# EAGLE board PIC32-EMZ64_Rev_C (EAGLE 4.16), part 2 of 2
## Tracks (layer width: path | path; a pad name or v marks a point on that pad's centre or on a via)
+5V  (via drill 0.3, 0.6)
  Top 0.508: 23.75,20.6 U2.4 | U2.1 21.59,18 v21.59,19.3 | 23.75,23.75 23.75,24 v28.45,24 v48.39,24 | R5.1 45.59,45.34 42.93,48.01 31.62,48.01 v31.37,47.75
  Top 1.016: C7.1 23.75,22.48 23.75,23.75 23.5,23.75 | 23.5,23.75 v22.35,23.75 12.7,23.75 v12.06,23.11 v11.43,22.48 | 23.75,20.6 23.75,22.23 C7.1 | 23.5,23.75 C7.1 | PWR.1 8.26,30.23 9.78,28.7 C30.1 9.14,27.43 | v17.27,38.23 14.99,38.23 v14.1,39.12
  Top 1.27: 9.14,27.43 FB1.1
  Bottom 0.254: U1.33 30.41,26.73 30.35,26.67 30.35,25.02 30.1,24.77 C34.2
  Bottom 0.508: v22.35,23.75 21.59,22.99 v21.59,19.3 | 2.16,38.58 2.16,38.73 2.35,38.73 U5.5 | 1.97,36.83 C9.1 | 18.67,41.91 5V/3.3V.1 | v28.45,24 C34.2 | v31.37,47.75 31.11,48.01 22.99,48.01 21.46,46.48 14.73,46.48 13.08,44.83 13.08,41.91 14.1,40.89 v14.1,39.12 | v48.39,24 R54.2
  Bottom 0.762: v17.27,38.23 17.27,39.5 18.67,40.89 18.67,41.91
  Bottom 1.016: 11.94,23.24 v12.06,23.11 v11.43,22.48 11.43,23.88 | 1.97,36.83 2.16,37.02 2.16,38.58 | 13.72,38.73 v14.1,39.12
  Bottom 1.27: 11.94,23.24 8.26,26.92 PWR.1 8.26,32.26 | 1.97,36.83 1.97,34.22 3.94,32.26 8.26,32.26 | 8.26,32.26 10.54,32.26 12.19,33.91 12.19,37.21 13.72,38.73
+5V_HOST_PWR
  Bottom 0.508: 5.71,45.09 C12.1
  Bottom 1.016: USB_HOST.1 8.61,45.09 5.71,45.09 4.57,45.09 4.19,45.09 L1.1
A_IN(AN4)
  Bottom 0.254: U1.12 45.31,28.73 51.82,22.23 67.06,22.23 R7.2
  Bottom 0.508: R7.2 C18.1
A_OUT(OC4)
  Bottom 0.254: U1.13 45.05,28.23 53.72,19.56 53.72,3.56 54.48,2.79 R18.1
AGND  (via drill 0.3 pad 0.25, 0.6, 0.6 pad 0.25)
  Top 0.508: v40.51,21.21 49.91,21.21 v51.44,19.68 | 75.02,23.33 MICROPHONE.5
  Top 0.762: C15.2 21.84,10.79 21.08,10.03 20.45,10.03 R16.2 19.94,9.4 C16.2 19.94,8.13 20.32,7.75 v21.59,7.75 | v57.53,18.54 52.58,18.54 v51.44,19.68 | v56.52,6.48 v56.52,8.64
  Top 1.016: 75.02,23.33 75.82,22.52 v75.82,18.03 75.82,13.2 | 75.82,13.2 HEADPHONES.5 | v75.82,7.37 75.82,13.2
  Bottom 0.254: C44.2 39.75,21.21 39.08,21.88 U1.20
  Bottom 0.508: SR1.3 47.88,19.68 R59.1 v51.44,19.68 | v40.51,21.21 C44.2 | C20.2 57.53,16.76 U3.4 | 57.53,17.91 R14.1 | C19.2 60.45,20.45 60.45,20.32 C2.2 | 56.01,11.68 C1.2 | C18.2 71.88,19.3 73.15,18.03 v75.82,18.03 | 67.44,4.57 U4.7 | C24.2 68.96,4.57 67.44,4.57 | 67.44,4.57 C23.2 | U4.1 57.78,3.3 C29.2 | 56.52,4.7 C22.2 | 56.52,5.59 C21.2 | v56.52,6.48 R23.1
  Bottom 0.762: v21.59,7.75 21.59,7.49 22.61,6.48 22.61,2.03 23.88,0.76 57.78,0.76 | 57.78,0.76 C29.2 57.28,3.05 56.52,3.81 56.52,4.7 56.52,5.59 v56.52,6.48 | 57.78,0.76 68.33,0.76 68.96,1.4 C24.2 | 60.45,20.45 58.04,20.45 57.53,19.94 v57.53,18.54 57.53,17.91 C20.2 57.28,17.02 56.01,15.75 56.01,11.68 56.01,9.14 v56.52,8.64
  Bottom 1.016: v75.82,7.37 72.52,4.06 69.09,4.06 C24.2
AREF
  Bottom 0.254: U1.16 45.66,26.73 47.37,25.02 R54.1
  Bottom 0.508: SR1.1 47.37,21.73 R58.2 R54.1
  Bottom 1.016: SR1.1 46.93,21.08 R55.2
CANH  (via drill 0.3)
  Top 0.508: v33.15,41.66 34.16,42.67 38.9,42.67 39.15,42.93
  Top 1.016: 39.15,42.93 CAN.3
  Bottom 0.508: 31.88,41.66 30.35,41.66 30.1,41.91 U7.7 | 31.88,41.66 v33.15,41.66 | 31.88,41.66 R22.2
CANL  (via drill 0.3)
  Top 0.508: 35.83,43.43 36.16,43.43 36.41,43.69 | v32.91,42.55 33.8,43.43 35.83,43.43 | 35.83,43.43 36.21,43.81
  Top 1.016: 36.41,43.69 CAN.2
  Bottom 0.508: v32.91,42.55 30.61,42.55 CAN_T.1 U7.6
CLKI
  Bottom 0.254: U1.31 33.58,22.48 CD2.3
D+  (via drill 0.3)
  Top 0.254: 17.91,29.72 18.54,29.08 20.57,29.08 20.83,29.34 v25.78,29.34
  Top 1.016: DEV_DP/HOST_DP.2 17.91,29.72
  Bottom 0.254: U1.37 26.52,28.73 25.91,29.34 v25.78,29.34
D-  (via drill 0.3)
  Top 0.254: 17.14,32.77 15.88,31.5 15.88,29.08 16.38,28.57 20.83,28.57 21.08,28.83 24.77,28.83 25.02,28.57 v25.78,28.57
  Top 1.016: 17.14,32.77 DEV_DM/HOST_DM.2
  Bottom 0.254: U1.36 26.13,28.23 v25.78,28.57
ETH_SHIELD  (via drill 0.6)
  Top 1.016: C6.2 62.74,25.91 62.87,26.04 | 66.04,42.92 LAN.GND2 70.87,42.92 | LAN.GND1 69.29,26.8 71.25,26.8
  Top 1.27: LAN.GND2 LAN.GND1 63.75,26.92 62.87,26.04
  Bottom 1.016: 69.34,28.7 v69.85,29.21
  Bottom 1.27: LAN.GND2 69.22,42.92 69.22,40.64 | LAN.GND1 69.34,26.93 69.34,28.7
  other vias: 72.39,36.83 73.66,38.1 71.12,38.1 71.12,35.56 73.66,35.56 72.39,34.29 71.12,33.02 73.66,33.02 72.39,31.75 69.85,31.75 69.85,34.29 69.85,36.83 69.85,39.37 68.58,40.64 68.58,38.1 68.58,35.56 68.58,33.02 67.31,41.91 74.93,36.83 74.93,34.29 76.2,35.56 76.2,33.02 77.47,34.29 77.47,36.83
  pour Top (isolate 0.508): 81.28,43.81 61.59,43.81 61.59,40.77 65.28,40.77 67.06,38.99 67.06,29.84 66.29,29.08 62.23,29.08 62.23,26.42 81.28,26.42
  pour Bottom (isolate 0.508): 82.55,43.81 61.59,43.81 61.59,40.77 65.28,40.77 67.06,38.99 67.06,29.84 66.29,29.08 62.23,29.08 62.23,26.42 82.55,26.42
  pour Bottom (isolate 2.286): 83.19,43.81 61.59,43.81 61.59,40.77 65.28,40.77 67.06,38.99 67.06,29.84 66.29,29.08 62.23,29.08 62.23,26.42 83.19,26.42
  pour Top (isolate 2.286): 81.92,43.81 61.59,43.81 61.59,40.77 65.28,40.77 67.06,38.99 67.06,29.84 66.29,29.08 62.23,29.08 62.23,26.42 81.92,26.42
GND  (via drill 0.3, 0.3 pad 0.25, 0.6, 0.6 pad 0.25)
  Top 0.254: v56.52,30.61 56.36,30.61 56.36,32.31 | 56.36,32.31 U6.24 | U6.25 57.5,33.17 58.17,32.51 C49.1 | 56.36,32.31 56.36,32.16 56.77,31.75 | USB_DEV.GND 5.65,21.72 5.97,21.72 | v23.62,26.29 23.37,26.04 20.83,26.04 19.68,24.89 18.54,24.89
  Top 0.406: v51.44,42.16 C52.1
  Top 0.508: 20.7,16.76 C13.2 | 27.43,30.23 v27.43,30.35 | 23.37,27.05 R25.1 | RM3.3.2 45.59,39.24 45.59,38.99 | 45.59,38.48 RM3.2.2 | 45.59,38.99 45.59,38.48 | 45.59,38.48 45.59,37.72 45.72,37.59 | 45.34,38.99 45.59,38.99 | v57.53,40.01 C5.2 | v59.31,40.13 C50.1 60.45,39.62 | v59.31,40.13 60.45,40.13 | 60.45,40.13 R51.1 | 60.45,40.13 60.58,40.13 | v45.21,30.86 47.37,30.86 48.01,30.23 49.91,30.23 v50.42,30.73 50.67,30.73 50.8,30.86 R50.1 | v58.29,31.5 C49.1 | 59.82,31.24 v60.45,31.24 | 59.82,31.24 C65.1 | 59.82,31.75 59.82,31.24 | C48.1 59.44,31.75 59.82,31.75 | 59.82,31.75 v60.45,31.75 | v59.31,40.13 59.56,40.39 | 59.56,40.39 60.07,40.89 v60.45,40.89 | 59.56,40.39 60.45,40.39 | C45.1 v49.91,34.29 v49.91,33.78 v50.55,33.78 C45.1
  Top 0.762: C7.2 21.72,22.35 22.61,21.46 v22.61,19.43 22.61,19.3 | 22.61,19.3 U2.2 22.61,17.02 v22.35,16.76 20.7,16.76 20.57,16.76 20.45,16.64 | 27.43,30.23 v27.43,27.56 26.92,27.05 v26.42,27.05 23.62,27.05 | 23.62,27.05 23.37,27.05 | 13.72,12.01 13.72,12.19 12.7,13.21 12.7,15.11 12.32,15.49 v10.29,15.49 | 22.61,19.3 24.26,19.3 v24.38,19.43 | v23.62,26.29 23.62,27.05 | v25.02,22.23 v29.72,22.23 v37.72,22.23 38.61,23.11 51.56,23.11 53.21,24.77 v56.52,24.77 | 45.72,37.59 RM3.1.2 | 13.72,12.01 MICRO-SD.6 19.1,12.01 v19.43,11.68 | v13.72,11.05 13.72,12.01
  Top 1.016: C7.2 R15.2 v14.48,22.48 v13.46,22.48 13.46,22.1 12.57,21.21 9.78,21.21 | 20.45,16.64 v20.45,16.38 C14.2 | UEXT.2 16.51,48.26 | v19.43,11.68 R16.1 | v34.45,49.02 44.83,49.02 | 44.83,49.02 PWR_LED.C LED1.C LED2.C LED3.C 57.53,49.02 | ICSP.3 64.9,48.26 64.14,49.02 57.53,49.02 | v28.07,45.97 29.97,45.97 30.73,45.22 CAN.1 | 31.37,0.89 27.05,0.89 v27.05,2.92 | 31.37,0.89 BUT1.P$2 | 31.37,0.89 44.07,0.89 | 44.07,0.89 BUT2.P$2 | 44.07,0.89 50.16,0.89 52.45,3.17 56.13,3.17 BUT3.P$2 | C54.1 v28.57,10.03 32.77,10.03 | 32.77,10.03 C55.1 | 49.28,10.03 C57.1 | 32.77,10.03 49.28,10.03 | C56.1 53.34,10.03 v49.91,10.03 49.28,10.03 | C51.1 51.44,41.4 v51.44,42.16 CD1.2 | v44.83,38.99 45.34,38.99 | 44.83,49.02 v44.83,47.62 | v57.53,47.62 57.53,49.02 | C46.1 56.01,30.1 v56.52,30.61 57.4,31.5 57.66,31.5 | C48.1 v58.29,31.5 57.66,31.5 | 57.66,31.5 56.77,31.5 | R51.1 60.45,40.39 v60.45,40.89 | v56.52,25.78 v57.78,25.78 59.18,25.78 C6.1 59.18,24.77 v57.78,24.77 v56.52,24.77 | 16.51,49.02 v17.78,49.02 | C30.2 11.56,29.72 PWR.2 | 9.78,21.21 v9.27,21.72 v8.26,21.72 v7.24,21.72 5.97,21.72 | 9.78,21.21 FB2.1 9.91,19.81 | v2.67,30.35 v2.67,29.21 | v27.05,5.33 25.91,6.48 v20.95,6.48 | RST.P$2 70.99,2.54 GND_PIN.P$1
  Top 1.524: USB_HOST.4 8.93,38.44 9.4,37.97 9.4,32.64 | 9.4,32.64 6.22,32.64 v3.94,30.35 v2.67,30.35 | PWR.2 10.79,31.24 9.4,32.64
  Bottom 0.254: U1.40 29.47,30.23 29.22,30.48 27.56,30.48 v27.43,30.35 | U1.35 27.6,27.73 v27.43,27.56 | U1.55 36.08,37.98 36.58,38.48 36.58,39.5 | 36.2,39.88 36.58,39.5 | U1.25 36.58,22.48 C38.2 | 38.08,36.44 38.08,37.95 37.59,38.44 37.59,39.5 | 38.08,36.44 U1.59 | 37.72,39.88 37.59,39.75 37.59,39.5 | 37.97,39.88 37.59,39.5 | 36.58,39.5 36.58,39.88 | U1.7 44.21,31.23 C37.2 | 38.08,36.44 38.08,34.95 38.48,34.54 | 3.81,36.96 4.06,37.21 4.45,37.21 5.08,37.85 6.35,37.85 7.37,38.86
  Bottom 0.406: 34.76,10.03 LCD.8 | 36.16,10.03 LCD.10 | C53.2 37.55,16.38 LCD.12 37.55,10.03 | 38.26,10.03 LCD.13 | 39.66,10.03 LCD.15 | 40.35,10.03 LCD.16 | 41.05,10.03 LCD.17 | 43.85,10.03 LCD.21 43.85,15.66 43.94,15.75 | 44.55,10.03 LCD.22 | 45.26,10.03 LCD.23 45.26,16.38 R44.1 | 45.95,10.03 LCD.24 | 46.66,10.03 LCD.25 | LCD.29 49.45,10.49 v49.91,10.03
  Bottom 0.508: 5.33,39.75 5.21,39.75 | 5.33,39.75 R9.1 | 5.33,39.75 R8.1 | C4.2 4.57,43.69 C12.2 6.48,42.93 6.48,42.67 | 2.29,24.61 2.29,24.64 0.64,26.29 0.64,29.97 0.76,30.1 0.76,30.35 | 0.76,30.35 0.76,37.85 R10.1 | C35.1 v27.43,27.56 | C35.1 27.43,25.91 | 27.43,25.91 C36.2 | 27.43,25.91 C34.1 | v27.43,30.35 C39.2 | 29.72,21.59 C82.2 | 12.32,0.89 C61.2 | v37.72,22.23 C38.2 | 27.18,27.05 C35.1 | 35.69,40.13 35.69,39.88 C40.2 36.2,39.88 36.58,39.88 37.72,39.88 37.97,39.88 C41.2 | 57.53,40.13 v59.31,40.13 59.31,41.02 | v49.91,34.29 v49.91,33.78 50.42,33.78 | 50.42,33.78 v50.55,33.78 | 50.42,33.78 52.83,33.78 | C37.2 v45.21,30.86 | v50.42,30.73 50.42,33.78 | R63.2 75.69,25.53 74.3,24.13 56.52,24.13 56.52,24.38 | 4.06,42.93 4.57,42.42 6.48,42.42 | v2.67,30.35 0.76,30.35
  Bottom 0.762: C4.2 4.06,42.93 4.06,42.67 3.3,41.91 U5.2 3.3,39.75 | 5.21,39.75 3.3,39.75 | C9.2 3.81,36.96 3.3,37.47 3.3,39.75 | v10.29,15.49 10.41,15.37 RM1.1.2 | C43.2 v13.72,11.05 | 24.26,41.91 R24.1 | 20.45,41.78 C32.2 24.26,41.91 | 24.26,41.91 25.53,43.18 25.53,44.96 26.16,45.59 | 26.16,45.59 R33.2 26.54,45.97 | v24.38,19.43 24.38,22.23 | 24.38,22.23 23.62,22.99 v23.62,26.29 | v28.07,45.97 26.54,45.97 | 26.54,45.97 26.16,45.59 | 24.38,22.23 v25.02,22.23 | v26.42,27.05 27.18,27.05 | v29.72,22.23 29.72,21.59 29.97,21.59 CD2.2 29.97,22.48 v29.72,22.23
  Bottom 1.016: 11.3,39.5 11.3,45.85 12.19,46.74 12.19,47.75 13.46,49.02 v34.45,49.02 CAN.1 34.45,43.41 35.69,42.16 35.69,40.13 | v19.43,11.68 20.45,12.7 v20.45,16.38 | v9.27,21.72 v8.26,21.72 | v20.95,6.48 20.32,7.11 17.53,7.11 15.24,4.83 v15.24,3.68 15.24,2.41 13.72,0.89 12.32,0.89 9.53,0.89 8.89,1.52 v8.89,3.94 | v27.05,2.92 27.05,8.51 v28.57,10.03 | v44.83,38.99 v44.83,47.62 v57.53,47.62 57.53,42.16 | 57.53,41.02 59.31,41.02 59.69,41.02 | 59.69,41.02 60.33,41.02 | 57.53,41.02 57.53,42.16 | 57.53,41.02 57.53,40.13 v57.53,40.01 57.15,39.62 57.15,31.24 | 57.15,31.24 v56.52,30.61 v56.52,25.78 56.52,24.38 | 57.53,42.16 v51.44,42.16 | 57.15,31.24 57.4,31.5 v58.29,31.5 | 59.69,41.02 59.69,38.61 | 60.33,41.02 v60.45,40.89 58.67,39.12 | 60.33,41.02 58.67,42.67 | PWR.2 10.79,27.3 13.46,24.64 v13.46,22.48 v14.48,22.48 | 6.48,39.75 5.33,39.75
  Bottom 1.27: 9.53,38.41 USB_HOST.4 7.82,38.41 7.37,38.86 6.48,39.75 6.48,42.42 6.48,42.67 | 9.53,38.41 L4.1 | 9.53,38.41 10.22,38.41 11.3,39.5
  other vias: 42.45,38.86 39.4,37.97 56.52,20.95 56.01,17.27 57.78,10.67 59.69,10.67 62.23,6.35 62.23,4.45 65.41,1.91 67.31,1.91 71.5,5.33 65.28,10.79 65.28,9.27 62.23,16.89 62.23,15.75 78.74,9.53 78.74,8.26 78.74,6.99 78.74,10.79 78.74,15.88 78.74,17.14 78.74,18.41 78.74,19.68 78.74,20.95 73.03,21.59 71.12,21.59 77.47,20.95 77.47,19.68 77.47,18.41 77.47,17.14 77.47,15.88 77.47,10.79 77.47,9.53 77.47,8.26 77.47,6.99 73.03,13.97 73.03,12.7 73.03,11.43 52.7,16.51 52.7,14.61 52.7,12.7 50.8,16.51 48.9,16.51 39.75,34.16 41.15,34.29 43.18,25.15 45.72,25.15 44.45,25.15 42.55,19.05 0.89,17.14 0.89,14.61 0.89,12.06 0.89,9.53 0.89,6.99 2.16,17.14 2.16,14.61 2.16,12.06 2.16,9.53 2.16,6.99 6.35,14.61 6.35,12.06 7.62,14.61 7.62,12.06 7.62,9.53 7.62,6.99 6.35,8.26 7.37,3.94 37.62,49.02 40.8,49.02 14.12,49.02 12.22,49.02 12.22,47.75 52.7,5.71 52.7,3.17 52.7,4.45 50.8,4.45 48.9,4.45 41.91,3.17 40.01,3.17 38.1,3.17 37.47,8.26 40.01,8.26 42.55,8.26 45.09,8.26 34.92,8.26 53.34,23.5 53.34,24.77 53.34,26.04 52.07,24.77 52.07,23.5 50.8,24.77 54.61,40.89 63.66,49.02 65.56,49.02 67.47,49.02 69.37,49.02 71.28,49.02 73.18,49.02 22.89,49.02 20.35,49.02 25.43,49.02 44.96,44.45 57.15,12.7 61.59,13.08 16.89,16.38 51.44,14.61
  pour Bottom (isolate 0.254, rank 2): 86.36,55.88 -7.62,55.88 -7.62,-5.08 86.36,-5.08
  pour Top (isolate 0.254, rank 2): 83.82,53.34 -5.08,53.34 -5.08,-2.54 83.82,-2.54
  pour Bottom (no thermals): 57.15,32.38 57.15,37.47 52.07,37.47 52.07,32.38
LEFT  (via drill 0.3)
  Top 0.508: MICROPHONE.2 64.77,23.61 v64.77,21.59
  Bottom 0.508: v64.77,21.59 R12.2 R4.1 C3.1 C19.1
MCIDAT1  (via drill 0.3)
  Top 0.508: MICRO-SD.8 14.62,14.21 14.35,14.48 v13.72,14.48
  Bottom 0.508: RM1.2.1 v13.72,14.48
MCIDAT2  (via drill 0.3)
  Top 0.508: v12.32,12.19 12.32,9.27 13.21,8.38 13.21,6.86 13.72,6.35 14.48,6.35 14.64,6.51 MICRO-SD.1
  Bottom 0.508: RM1.4.1 12.83,12.7 v12.32,12.19
N$1
  Bottom 0.508: 20.45,43.05 21.08,43.05 21.21,43.18 U7.3 | 20.45,43.05 18.03,43.05 17.78,42.8 5V/3.3V.2 | 20.45,43.05 C32.1
N$2
  Top 0.508: 21.84,27.05 R25.2
  Top 1.016: DEV_ID/HOST_ID.3 20.07,27.05 21.84,27.05
N$4  (via drill 0.3)
  Top 1.016: MICRO-SD.11 14.49,1.91 13.46,0.89 5.15,0.89 MICRO-SD.13 3.43,2.73 3.43,15.75 4.06,16.38 5.15,16.38 MICRO-SD.12 5.4,16.76 13.21,16.76 v13.46,16.51 MICRO-SD.10
  Bottom 0.508: v13.46,16.51 R27.1
N$5
  Bottom 0.508: R57.1 C61.1
N$6
  Top 0.254: USB_DEV.VBUS 5.49,24.67 5.84,25.02
  Top 1.016: 7.62,25.02 FB1.2 8,25.53 6.35,25.53 5.84,25.02 7.62,25.02
N$7
  Bottom 0.508: R52.2 23.37,44.83 22.99,44.45 U7.4 22.1,44.45
N$8
  Top 0.508: R5.2 PWR_LED.A
N$9  (via drill 0.3)
  Top 0.508: v50.42,8.51 C56.2
  Bottom 0.406: LCD.28 48.76,9.03 49.28,8.51 v50.42,8.51
N$10
  Bottom 0.406: LCD.4 31.95,15.95 C60.1
N$11
  Bottom 0.508: U7.5 28.19,44.45 29.46,45.72 FB3.1
N$13
  Bottom 0.406: LCD.14 38.95,16.38 C53.1
  Bottom 0.508: C53.1 39.12,16.26 R40.2 R41.1
N$14
  Bottom 0.508: U4.4 61.09,7.11 61.47,7.49 C25.2 R21.2
  Bottom 1.016: C25.2 R20.1
N$15
  Bottom 0.508: U4.2 57.78,4.57 C29.1 58.8,5.84 U4.3
N$16  (via drill 0.6)
  Top 0.508: v67.18,3.3 v67.18,6.86
  Bottom 0.508: U4.8 v67.18,3.3
  Bottom 0.762: C27.1 68.58,8.26 v67.18,6.86
  Bottom 1.27: C27.1 C66.1
N$17  (via drill 0.6)
  Top 1.016: UEXT.4 19.05,47.62 v18.03,47.62
  Bottom 1.016: D2.C 14.48,47.62 v18.03,47.62
N$18
  Bottom 0.508: R19.2 C21.1 R17.2
N$22
  Bottom 0.508: R17.1 C22.1 R18.2
N$23
  Top 0.508: R28.1 LED1.A
N$24
  Bottom 0.508: U4.5 63.63,7.11 63.25,7.49 C25.1
  Bottom 1.016: C25.1 R20.2
N$25
  Bottom 0.508: C26.1 R21.1
N$26
  Top 0.508: R29.1 LED2.A
N$27
  Top 0.762: R30.1 LED3.A
N$31
  Top 0.254: U6.19 53.86,31.64 53.21,30.99 52.58,30.99 R50.2
  Top 0.508: R49.2 R50.2
N$32
  Bottom 0.406: LCD.26 47.35,16.38 R44.2
N$36
  Bottom 0.508: R59.2 49.42,20.7 SR1.2 48.39,21.73 R58.1
N$37
  Bottom 0.406: LCD.2 30.55,15.04 30.23,15.37 29.59,15.37 28.57,16.38 C59.1
N$39
  Bottom 0.406: LCD.3 31.25,15.99 C59.2
N$40
  Bottom 0.406: LCD.5 32.66,15 33.02,15.37 33.78,15.37 34.67,16.26 C60.2
N$41  (via drill 0.3 pad 0.25)
  Top 0.254: U6.29 v58.8,35.17 v58.8,35.18
  Top 0.508: v58.8,35.18 R39.1
  Bottom 0.254: v58.8,35.18 60.33,35.18 62.28,33.22 63.93,33.22 64.77,32.38 64.77,31.37 65.02,31.11
  Bottom 0.508: LAN.1 65.67,30.47 65.02,31.11
N$42  (via drill 0.3 pad 0.25)
  Top 0.254: U6.28 57.91,34.67 58.17,34.42 v58.8,34.42
  Top 0.508: v58.8,34.42 R38.1
  Bottom 0.254: v58.8,34.42 60.33,34.42 61.98,32.77 63.63,32.77 64.26,32.13 64.26,31.24 64.14,31.11 63.75,31.11
  Bottom 0.508: LAN.2 63.15,31.72 63.75,31.11
N$44  (via drill 0.3 pad 0.25)
  Top 0.254: U6.31 57.64,36.17 58.17,36.7 v58.8,36.7
  Top 0.508: v58.8,36.7 R37.1
  Bottom 0.254: v58.8,36.7 60.2,36.7 60.58,37.08 60.58,39.24 62.36,41.02 65.02,41.02 65.53,40.51 65.53,39.12
  Bottom 0.508: LAN.7 65.53,38.1 65.53,39.12
N$49  (via drill 0.3 pad 0.25)
  Top 0.254: U6.30 57.9,35.67 58.17,35.94 v58.8,35.94 | 59.18,35.94 R36.1
  Top 0.508: v58.8,35.94 59.18,35.94
  Bottom 0.254: v58.8,35.94 60.2,35.94 61.09,36.83 61.09,38.99 62.61,40.51 64.77,40.51 65.02,40.26 65.02,39.75 64.64,39.37
  Bottom 0.508: LAN.8 64.64,39.37
N$53
  Top 0.254: U6.2 55.86,37.95 56.01,38.1 57.28,38.1 58.67,39.5 58.67,40.51 60.07,41.91 61.34,41.91 63.37,43.94 74.3,43.94 75.82,42.42
  Top 1.016: 75.82,42.42 76.71,41.53 LAN.KG
N$54
  Top 0.254: U6.3 55.36,38.22 55.75,38.61 57.02,38.61 58.17,39.75 58.17,40.77 59.82,42.42 61.09,42.42 63.12,44.45 74.68,44.45 75.69,43.43 77.98,43.43 79.38,42.04 79.38,30.55 78.23,29.41
  Top 1.016: 78.23,29.41 LAN.AY
N$55
  Top 0.254: U6.32 57.38,36.67 58.42,37.72 60.45,37.72 R51.2
N$56  (via drill 0.3)
  Top 0.508: 58.42,30.48 v58.17,30.48 v58.17,29.97 58.17,29.21 R34.1 58.42,30.48 | 58.42,30.48 58.67,30.48 | 58.67,30.48 C65.2 | 58.67,30.48 58.67,29.21
  Bottom 0.508: v58.17,30.48 58.17,30.23 | v58.17,30.48 v58.17,29.97 v58.17,30.48
  Bottom 0.762: LAN.6 63.15,36.16 65.69,33.62 LAN.3
  Bottom 1.016: 58.17,30.23 62.74,30.23 64.01,28.96 66.42,28.96 67.18,29.72 67.18,31.52 LAN.3
N$57
  Bottom 0.508: R63.1 75.95,30.86
  Bottom 1.016: LAN.KY 77.14,30.86 75.95,30.86
N$58
  Top 0.254: U6.6 53.86,38.22 53.47,38.61 52.2,38.61 51.44,39.37 C52.2
  Top 0.508: C51.2 50.29,39.88 51.44,39.88 C52.2
N$59  (via drill 0.3)
  Top 0.254: U6.1 56.36,37.59 57.53,37.59 58.55,38.61 C50.2 59.69,38.99 61.59,38.99 | U6.27 57.65,34.17 C49.2
  Top 0.508: R37.2 61.47,36.7 61.59,36.7 61.59,38.99 61.59,41.27 v63.63,43.31 | 61.47,35.94 R36.2 | 61.47,35.18 R39.2 | 61.47,34.42 R38.2 | 59.44,33.53 C48.2 | 59.44,33.53 C49.2 | 61.47,33.53 59.44,33.53
  Top 0.762: 61.47,36.7 61.47,35.94 61.47,35.18 61.47,34.42 61.47,33.53 61.47,30.48 R34.2
  Top 1.016: R34.2 60.2,27.43 L6.1
  Bottom 0.508: v63.63,43.31 64.39,44.07 73.28,44.07 75.69,41.66 R35.1
N$64
  Top 0.508: U2.3 23.75,17.81 23.75,17.65
  Top 1.016: 23.75,15.37 23.75,15.3 L2.1 23.11,15.88 23.75,16.51 | 23.75,16.51 23.75,15.37 | 23.75,16.51 23.75,17.65 24.38,17.02 24.38,15.37 23.75,15.37
N$65
  Bottom 0.508: R35.2 75.95,38.99
  Bottom 1.016: LAN.AG 77.09,38.99 75.95,38.99
N$66
  Top 0.508: U2.5 21.66,20.7 21.34,20.7 | R15.1 19.68,20.7 R6.2 C8.2 20.45,20.7
  Top 1.016: R15.1 20.45,20.7 21.34,20.7
N$75
  Bottom 0.508: R22.1 31.88,43.94 CAN_T.2
N$115
  Bottom 0.508: U5.3 4.25,41.27 R9.2
N$116  (via drill 0.6)
  Top 0.762: MICRO-SD.4 14.26,9.81 v13.72,9.27
  Bottom 0.762: C43.1 12.57,9.27 v13.72,9.27
  Bottom 1.27: C43.1 L5.2
N$137
  Bottom 0.508: U5.1 2.16,41.05 2.16,41.27 R3.2
  Bottom 1.016: C4.1 2.16,43.18 2.16,41.27
  Bottom 1.27: C4.1 L1.2
N$266
  Top 1.27: USB_HOST.P$2 4.57,46.33 4.57,37.49 USB_HOST.P$1
  Bottom 1.27: USB_HOST.P$1 7.52,34.54 L4.2
N$550
  Bottom 0.254: C3.2 61.21,17.14 61.21,15.62 61.09,15.49
  Bottom 0.508: R1.1 R14.2 C3.2 | U3.3 61.09,15.49
N$553
  Bottom 0.508: R4.2 R2.1 62.99,20.32 C2.1
N$554
  Bottom 0.254: 62.23,14.73 62.36,14.86 62.53,14.86 | 62.53,14.86 69.47,14.86 70.53,15.92 Z2.C | 62.53,14.86 62.28,14.61
  Bottom 0.508: R13.2 58.17,14.22 U3.2 61.72,14.22 62.23,14.73 | R11.1 69.98,17.78 C17.2
  Bottom 1.016: Z2.C 70.36,15.92 R11.1
N$555
  Bottom 0.508: C20.1 57.02,14.73 R13.1
N$556
  Bottom 0.508: R7.1 C17.1 68.96,17.78 R11.2 | U3.6 68.33,15.49 Z1.C
  Bottom 1.016: Z1.C 68.58,15.92 R11.2
N$557
  Bottom 1.27: Z1.A Z2.A
N$559  (via drill 0.6)
  Top 1.016: HEADPHONES.2 65.51,12.19 70.36,12.19 v72.26,10.29 72.26,7.45 HEADPHONES.3
  Bottom 1.016: v72.26,10.29 C66.2
  Bottom 1.27: C66.2 C27.2
N$561
  Bottom 0.508: C26.2 57.53,6.86 56.9,7.49 R23.2 R19.1
PGEC2  (via drill 0.3)
  Top 0.254: v37.34,33.78 37.34,34.16 37.08,34.42 37.08,35.43 34.8,37.72 34.8,39.37 35.43,40.01 40.77,40.01 42.29,41.53 47.24,41.53 49.91,44.2 56.77,44.2 57.53,44.96 68.2,44.96 68.96,45.72
  Top 1.016: 68.96,45.72 ICSP.5
  Bottom 0.254: U1.17 40.58,26.09 37.47,29.21 37.47,33.02 37.34,33.15 v37.34,33.78
PGED2  (via drill 0.3)
  Top 0.254: v36.58,33.78 36.58,35.18 34.29,37.47 34.29,39.62 35.18,40.51 40.51,40.51 42.04,42.04 46.99,42.04 49.66,44.7 56.52,44.7 57.28,45.47 66.17,45.47 66.67,45.97
  Top 1.016: 66.67,45.97 ICSP.4
  Bottom 0.254: U1.18 40.08,25.83 36.96,28.96 36.96,32.77 36.58,33.15 v36.58,33.78
PHYAD1
  Top 0.254: U6.7 53.36,37.95 53.21,38.1 51.94,38.1 51.31,38.73 49.66,38.73 49.15,39.24 RM3.3.1
PHYAD2
  Top 0.254: U6.8 52.86,37.59 51.69,37.59 51.05,38.23 49.4,38.23 49.15,38.48 RM3.2.1
RB1/#ETH_INT(INT4)  (via drill 0.3)
  Top 0.254: U6.18 53.36,31.9 53.09,31.62 50.16,31.62 R32.1 50.04,31.37 49.53,30.86 48.26,30.86 47.5,31.62 42.55,31.62 41.66,30.73 41.66,28.7 41.27,28.32 v41.27,27.05
  Bottom 0.254: U1.15 41.45,27.23 v41.27,27.05
RB2(USB_HOST_FAULT)  (via drill 0.3)
  Top 0.254: v10.79,46.74 10.79,45.85 13.21,43.43 13.21,38.61 14.48,37.34 19.56,37.34 21.46,35.43 21.46,32.38 22.48,31.37 25.4,31.37 25.53,31.5 29.59,31.5 30.86,30.23 v34.8,30.23 | v34.8,27.69 v40.64,27.69
  Bottom 0.254: v34.8,30.23 v34.8,27.69 | U1.14 40.68,27.73 v40.64,27.69 | R3.1 1.02,40.26 0.51,40.77 0.51,45.85 1.02,46.35 4.95,46.35 5.33,45.97 7.11,45.97 7.87,46.74 v10.79,46.74
  Bottom 0.508: R10.2 R3.1
RB5(USB_HOST_EN)  (via drill 0.3)
  Top 0.254: v6.1,38.48 6.1,42.8 7.49,44.2 11.68,44.2 12.7,43.18 12.7,38.35 14.22,36.83 19.3,36.83 20.95,35.18 20.95,32.13 22.23,30.86 25.65,30.86 25.78,30.99 29.34,30.99 31.5,28.83 v40.64,28.83
  Bottom 0.254: U1.11 41.68,29.23 41.27,28.83 v40.64,28.83
  Bottom 0.508: U5.4 4.25,38.48 R8.2 v6.1,38.48
RB8(LED1)  (via drill 0.3)
  Top 0.254: v35.81,33.78 35.81,35.18 33.78,37.21 33.78,39.88 34.92,41.02 40.26,41.02 41.78,42.55 46.74,42.55 R28.2
  Bottom 0.254: U1.21 38.58,26.57 36.45,28.7 36.45,32.51 35.81,33.15 v35.81,33.78
RB9(LED2)  (via drill 0.3, 0.3 pad 0.25)
  Top 0.254: v35.05,33.78 35.05,35.18 33.27,36.96 33.27,40.13 34.67,41.53 40.01,41.53 41.53,43.05 46.23,43.05 v48.51,45.34
  Top 0.508: v51.56,45.34 R29.2
  Bottom 0.254: U1.22 38.08,26.31 35.94,28.45 35.94,32.26 35.05,33.15 v35.05,33.78
  Bottom 0.508: v48.51,45.34 v51.56,45.34
RB10(LED3)  (via drill 0.3, 0.3 pad 0.25)
  Top 0.254: v34.29,33.78 34.29,35.18 32.77,36.7 32.77,40.39 34.42,42.04 39.75,42.04 41.27,43.56 45.97,43.56 47.75,45.34 v47.75,46.1
  Top 0.508: v54.74,45.34 R30.2
  Bottom 0.254: U1.23 37.58,26.05 35.43,28.19 35.43,32 34.29,33.15 v34.29,33.78
  Bottom 0.508: v47.75,46.1 53.98,46.1 v54.74,45.34
RB11/EPHY-RST#  (via drill 0.3)
  Top 0.254: v36.58,26.16 v50.93,26.16
  Top 0.508: v50.93,29.97 R49.1
  Bottom 0.254: U1.24 37.08,25.66 v36.58,26.16 | v50.93,26.16 v50.93,29.97
RB12(BUT1)  (via drill 0.3)
  Top 0.508: BUT1.P$1 23.62,2.92 v25.02,2.92
  Bottom 0.254: U1.27 35.58,18.69 34.67,17.78 27.81,17.78 27.56,17.53 27.56,14.1 26.16,12.7 26.16,4.06 v25.02,2.92
RB13(BUT2)  (via drill 0.3)
  Top 0.254: v25.02,3.81 34.49,3.81 | 34.49,3.81 34.67,3.81 34.8,3.68 | 34.49,3.81 34.75,3.56
  Top 0.508: 34.8,3.68 BUT2.P$1
  Bottom 0.254: U1.28 35.08,18.95 34.42,18.29 27.56,18.29 27.05,17.78 27.05,14.35 25.65,12.95 25.65,4.45 v25.02,3.81
RB14(BUT3)  (via drill 0.3)
  Top 0.254: v24.51,4.45 46.56,4.45 | 46.56,4.45 46.74,4.45 46.86,4.32 | 46.56,4.45 46.81,4.19
  Top 0.508: 46.86,4.32 BUT3.P$1
  Bottom 0.254: U1.29 34.58,19.27 34.11,18.8 27.3,18.8 26.54,18.03 26.54,14.61 25.15,13.21 25.15,5.08 v24.51,4.45
RB15/EMDC  (via drill 0.3)
  Top 0.254: v34.29,32 34.42,32.13 52.83,32.13 52.86,32.16 U6.17
  Bottom 0.254: U1.30 34.08,31.79 v34.29,32
RC13/C1RX  (via drill 0.3)
  Top 0.254: v28.57,39.12 28.57,43.31 28.07,43.81 24.51,43.81 v24.38,43.94
  Bottom 0.254: U1.47 29.52,33.73 28.57,34.67 v28.57,39.12
  Bottom 0.508: R33.1 R52.1 v24.38,43.94
RC14/C1TX  (via drill 0.3)
  Top 0.254: v29.21,37.72 23.75,37.72 22.86,38.61 v22.86,40.01
  Bottom 0.254: U1.48 29.78,34.23 29.08,34.92 29.08,37.59 v29.21,37.72
  Bottom 0.508: v22.86,40.01 22.86,40.64 U7.1
RC15/CAN_CTRL  (via drill 0.3)
  Top 0.254: v24.77,23.24 v32.13,23.24
  Bottom 0.254: U1.32 33.08,24.19 v32.13,23.24 | v24.77,23.24 24.51,23.5 24.51,27.43 24.13,27.81 24.13,30.35 26.16,32.38 26.16,36.96 25.02,38.1 25.02,38.86 25.27,39.12 R24.2
  Bottom 0.508: R24.2 25.27,40.39 25.53,40.64 U7.8 27.43,40.64
RD0/U4RX  (via drill 0.3)
  Top 0.254: v14.48,44.58 17.02,44.58 17.78,43.81 17.78,39.12 18.92,37.97 19.68,37.97 21.46,36.2 22.99,36.2 23.24,35.94 27.05,35.94 27.3,36.2 v27.94,36.2
  Bottom 0.254: U1.46 29.25,33.23 27.94,34.54 v27.94,36.2
  Bottom 0.508: R46.1 14.22,42.29 | D2.A v14.48,44.58
  Bottom 1.016: 14.22,42.29 14.22,43.69 D2.A
RD1/EMDIO  (via drill 0.3)
  Top 0.254: U6.16 51.72,33.17 51.18,32.64 48.26,32.64 | 48.26,32.64 RM2.4.2 | v32.89,32.64 48.26,32.64
  Bottom 0.254: U1.49 33.08,35.49 32.77,35.18 32.77,32.77 v32.89,32.64
RD2/SDO2(MOSI2)  (via drill 0.3)
  Top 0.254: v22.86,34.54 30.86,34.54 v31.88,35.56
  Top 0.508: MICRO-SD.3 14.55,8.71 v13.97,8.13
  Bottom 0.254: U1.50 33.58,37.16 33.27,37.47 32.13,37.47 31.88,37.21 v31.88,35.56 | v22.86,34.54 20.95,32.64 20.95,26.16 15.62,20.83 15.62,13.97 14.61,12.95 14.61,8.76
  Bottom 0.508: R26.1 13.21,7.37 v13.97,8.13 14.61,8.76
RD3/SDI2(MISO2)  (via drill 0.3)
  Top 0.254: v22.86,35.43 28.57,35.43 28.96,35.81 v30.35,35.81
  Top 0.508: v13.72,13.72 13.97,13.72 14.57,13.11 MICRO-SD.7
  Bottom 0.254: U1.51 34.08,37.42 33.53,37.97 31.88,37.97 31.11,37.21 31.11,36.58 v30.35,35.81 | v22.86,35.43 18.41,30.99 18.41,24.38 15.11,21.08 15.11,14.61 14.22,13.72
  Bottom 0.508: RM1.3.1 v13.72,13.72 14.22,13.72
RD4/U4TX  (via drill 0.3)
  Top 0.254: UEXT.3 19.05,39.5 21.84,36.7 23.24,36.7 23.5,36.45 26.8,36.45 27.18,36.83 28.57,36.83 28.83,36.58 v30.23,36.58
  Bottom 0.254: v30.23,36.58 30.61,36.96 30.61,37.72 31.37,38.48 33.78,38.48 34.58,37.68 U1.52
RD5/SDO4(MOSI4)  (via drill 0.3)
  Top 0.254: UEXT.8 24.13,45.97 25.15,44.96 29.46,44.96 30.48,43.94 v30.48,39.12
  Bottom 0.254: U1.53 35.08,37.95 33.91,39.12 v30.48,39.12
RD9/#SS4  (via drill 0.3, 0.6)
  Top 0.254: v29.08,44.07 29.59,43.56 v29.59,39.12
  Top 1.016: v25.53,46.99 26.67,46.99 UEXT.10
  Bottom 0.254: U1.43 32.11,31.73 32.26,31.88 32.26,34.54 32,34.8 30.1,34.8 29.59,35.31 29.59,36.96 29.84,37.21 29.84,38.86 v29.59,39.12 | v29.08,44.07 29.08,44.32 29.59,44.83 30.23,44.83 30.48,45.09 30.48,47.12 30.23,47.37 27.81,47.37 27.43,46.99
  Bottom 0.508: R48.1 21.72,45.59 23.11,46.99 v25.53,46.99 27.43,46.99
RD10/SCK4  (via drill 0.3)
  Top 0.762: v26.67,38.48 UEXT.9
  Bottom 0.254: U1.44 28.73,32.23 26.67,34.29 v26.67,38.48
RD11/SDI4(MISO4)  (via drill 0.3)
  Top 0.508: v25.65,38.35 24.26,38.35 24.13,38.48
  Top 0.762: 24.13,38.48 UEXT.7
  Bottom 0.254: U1.45 28.99,32.73 27.3,34.42 27.3,38.86 27.05,39.12 26.42,39.12 v25.65,38.35
RE0/ERXD1  (via drill 0.3, 0.3 pad 0.25)
  Top 0.254: U6.10 51.58,36.17 51.05,36.7 49.15,36.7 48.51,36.07 RM2.1.2 | v37.47,37.59 38.48,36.58 v41.27,36.58
  Top 0.508: v47.75,36.58 RM2.1.2
  Bottom 0.254: U1.58 37.58,37.48 v37.47,37.59 | v41.27,36.58 v47.75,36.58
RE1/ERXD0  (via drill 0.3 pad 0.25)
  Top 0.254: U6.11 51.32,35.67 50.93,36.07 49.91,36.07 v49.78,35.94 49.02,35.18 | RM2.2.2 48.13,35.18 | v38.99,35.05 39.75,35.81 v41.27,35.81
  Top 0.508: 49.02,35.18 RM2.2.2
  Bottom 0.254: U1.61 39.08,35.14 v38.99,35.05 | v41.27,35.81 49.66,35.81 v49.78,35.94
RE2/ECRSDV  (via drill 0.3 pad 0.25)
  Top 0.254: v49.15,34.42 49.28,34.29 49.28,33.4 49.53,33.15 50.93,33.15 51.45,33.67 U6.15
  Top 0.508: v49.15,34.42 RM2.3.2
  Bottom 0.254: U1.62 39.58,35.22 39.75,35.05 44.96,35.05 45.59,34.42 v49.15,34.42
RE3/EREFCLK  (via drill 0.3 pad 0.25)
  Top 0.254: U6.5 54.36,38.48 CD1.3 53.21,39.5
  Top 0.508: v52.2,39.5 53.21,39.5
  Bottom 0.254: v52.2,39.5 51.05,40.64 49.02,40.64 48.64,40.26 48.64,38.23 48.13,37.72 40.64,37.72 40.08,37.16 U1.63
RE4/ERXERR/PHYAD0  (via drill 0.3 pad 0.25)
  Top 0.254: U6.13 51.44,34.67 v51.31,34.54
  Top 0.508: RM3.1.1 48.51,37.59 v48.51,36.96
  Bottom 0.254: U1.64 40.58,36.9 40.89,37.21 48.26,37.21 v48.51,36.96 48.77,36.7 50.29,36.7 51.31,35.69 v51.31,34.54
RE5/ETXEN  (via drill 0.3)
  Top 0.254: U6.21 54.86,31.87 53.85,30.86 53.85,29.84 53.34,29.34 48.13,29.34 v48.01,29.46
  Bottom 0.254: U1.1 44.89,34.23 48.01,31.11 v48.01,29.46
RE6/ETXD0  (via drill 0.3)
  Top 0.254: v47.12,29.46 47.75,28.83 53.59,28.83 54.36,29.59 54.36,30.61 55.36,31.61 U6.22
  Bottom 0.254: U1.2 44.63,33.73 47.12,31.24 v47.12,29.46
RE7/ETXD1  (via drill 0.3)
  Top 0.254: U6.23 55.86,31.35 54.86,30.35 54.86,29.34 53.85,28.32 47.37,28.32 v46.23,29.46
  Bottom 0.254: U1.3 44.37,33.23 46.23,31.37 v46.23,29.46
RESET  (via drill 0.3, 0.3 pad 0.25)
  Top 0.254: v19.05,9.4 19.05,8.51 16.13,5.59 13.46,5.59 v9.91,2.03 | v38.1,33.78 38.1,34.16 37.59,34.67 37.59,35.69 35.31,37.97 35.31,39.12 35.69,39.5 41.02,39.5 42.55,41.02 47.5,41.02 50.16,43.69 57.02,43.69 57.66,44.32 v59.82,44.32 | v24.38,18.41 25.53,18.41 25.91,18.8 v41.15,18.8 41.91,18.03 43.69,18.03 46.1,15.62 60.33,15.62 62.87,13.08 62.87,11.05 63.37,10.54 63.37,4.06 62.48,3.17
  Top 1.016: RST.P$1 61.85,2.54 62.48,3.17
  Bottom 0.254: 38.1,30.23 U1.9 | 38.1,30.23 v38.1,33.78 | 38.1,30.23 38.1,29.34 41.15,26.29 v41.15,18.8 | v24.38,18.41 24.26,18.29 24.26,13.84 19.81,9.4 v19.05,9.4
  Bottom 0.508: R57.2 R56.2 v9.91,2.03
  Bottom 0.762: v59.82,44.32 ICSP.1
RF0(SD_CP)  (via drill 0.3)
  Top 0.254: v33.53,34.92 32.38,33.78 22.61,33.78 22.1,34.29 v22.1,35.56
  Top 0.508: MICRO-SD.9 15.32,15.37 v13.72,15.37
  Bottom 0.254: v33.53,34.92 33.66,35.05 36.45,35.05 36.58,35.18 U1.56 | v22.1,35.56 16.38,35.56 15.88,35.05 15.88,22.61 14.61,21.34 14.61,16.26 v13.72,15.37
  Bottom 0.508: RM1.1.1 v13.72,15.37
RF1(#LCD_RST)  (via drill 0.3)
  Top 0.254: v28.83,19.43 v40.26,19.43
  Bottom 0.254: U1.57 37.08,34.92 36.7,34.54 34.16,34.54 33.53,33.91 33.53,26.8 32.13,25.4 32.13,24.64 31.11,23.62 29.84,23.62 28.83,22.61 v28.83,19.43
  Bottom 0.508: v40.26,19.43 R40.1
RF4/SDA5  (via drill 0.3)
  Top 0.254: v25.4,16.26 v42.55,16.26
  Bottom 0.254: v25.4,16.26 25.4,17.02 25.53,17.14 25.53,18.54 26.42,19.43 26.42,23.37 25.53,24.26 25.53,27.94 25.15,28.32 25.15,29.84 26.29,30.99 29.46,30.99 29.72,30.73 U1.41
  Bottom 0.406: LCD.19 42.45,15.15 42.55,15.24 v42.55,16.26 | 43.16,16.26 LCD.20
  Bottom 0.508: v42.55,16.26 43.16,16.26 R43.1
RF5/SCL5  (via drill 0.3)
  Top 0.254: v25.4,15.37 26.42,15.37 26.67,15.62 v41.78,15.62
  Bottom 0.254: U1.42 29.98,31.23 29.72,31.5 26.04,31.5 24.64,30.1 24.64,28.07 25.02,27.69 25.02,24 25.91,23.11 25.91,19.68 25.02,18.8 25.02,17.4 24.77,17.14 24.77,16 v25.4,15.37
  Bottom 0.356: R42.1 v41.78,15.62 41.76,15.59 LCD.18
RG6/SCK2  (via drill 0.3)
  Top 0.254: v41.02,33.27 39.5,33.27 39.37,33.15 33.4,33.15 33.27,33.27 24.64,33.27 v23.62,32.26
  Top 0.508: MICRO-SD.5 15.38,10.92 v17.78,10.92
  Bottom 0.254: v17.78,10.92 17.78,11.43 19.3,12.95 19.3,21.97 19.43,22.1 | 19.43,22.1 22.73,25.4 22.73,31.37 v23.62,32.26 | U1.4 41.56,32.73 v41.02,33.27 | 19.43,22.1 19.43,21.79
RG7/SDA4  (via drill 0.3)
  Top 0.254: v24.77,32 29.84,32 30.99,30.86 v40.39,30.86 | v20.32,39.75 20.32,43.18 19.94,43.56 v19.94,44.7
  Top 0.508: v19.94,44.7 21.59,44.7 21.59,44.96
  Top 1.016: 21.59,44.96 UEXT.6
  Bottom 0.254: U1.5 40.87,32.23 40.39,31.75 v40.39,30.86 | v24.77,32 24.77,36.2 21.72,39.24 20.83,39.24 v20.32,39.75
  Bottom 0.508: v19.94,44.7 R47.1
RG8/SCL4  (via drill 0.3)
  Top 0.254: v25.02,37.08 23.88,37.08 23.75,37.21 22.99,37.21 21.59,38.61 | v41.02,31.5 39.37,31.5 39.24,31.37 31.24,31.37 29.97,32.64 v25.4,32.64
  Top 0.508: 21.59,42.8 v20.57,43.81
  Top 1.016: 21.59,42.8 UEXT.5 21.59,38.61
  Bottom 0.254: U1.6 41.26,31.73 v41.02,31.5 | v25.4,32.64 25.4,36.7 v25.02,37.08
  Bottom 0.508: v20.57,43.81 R45.1
RG9/#SS2  (via drill 0.3)
  Top 0.254: v32.89,29.46 v41.02,29.46 | 16.38,7.62 17.27,7.62 v18.41,8.76
  Top 0.508: 16.38,7.62 MICRO-SD.2 14.6,7.61 v14.1,7.11
  Bottom 0.254: v18.41,8.76 19.94,8.76 26.04,14.86 26.04,18.29 27.05,19.3 27.69,19.3 28.32,19.94 28.32,22.86 29.59,24.13 30.86,24.13 31.62,24.89 31.62,25.65 32.89,26.92 v32.89,29.46 | U1.10 41.29,29.73 v41.02,29.46
  Bottom 0.508: R31.1 13.59,6.6 v14.1,7.11
RIGHT  (via drill 0.3)
  Top 0.508: MICROPHONE.3 73.22,17.91 v66.8,17.91
  Bottom 0.508: R12.1 v66.8,17.91
RMIISEL  (via drill 0.3 pad 0.25)
  Top 0.254: U6.9 51.84,36.67 50.93,37.59 v49.28,37.59
  Top 0.508: v49.28,40.01 48.26,40.01 RM3.4.1
  Bottom 0.508: v49.28,37.59 v49.28,40.01
USB_DEV_DM
  Top 0.254: 13.21,32.89 12.57,32.26 12.57,27.05 9.53,24 6.22,24 6.21,24.02 USB_DEV.D-
  Top 1.016: 13.21,32.89 DEV_DM/HOST_DM.1
USB_DEV_DP
  Top 0.254: 13.72,30.48 13.08,29.84 13.08,26.8 9.78,23.5 6.48,23.5 6.35,23.37 USB_DEV.D+
  Top 1.016: 13.72,30.48 DEV_DP/HOST_DP.1
USB_DEV_ID
  Top 0.254: USB_DEV.ID 5.32,22.73 10.16,22.73 13.21,25.78 13.72,25.78
  Top 1.016: 13.72,25.78 DEV_ID/HOST_ID.1
USB_HOST_DM
  Top 0.254: 19.68,35.18 18.67,36.2 13.34,36.2 11.94,37.59 11.94,41.15 10.16,42.93
  Top 1.016: 19.68,35.18 DEV_DM/HOST_DM.3
  Top 1.27: USB_HOST.2 8.93,42.93 10.16,42.93
USB_HOST_DP
  Top 0.254: 18.41,31.75 18.41,35.31 18.03,35.69 13.08,35.69 11.43,37.34 11.43,40.64 11.18,40.89 10.16,40.89
  Top 1.27: 18.41,31.75 DEV_DP/HOST_DP.3 | USB_HOST.3 8.93,40.89 10.16,40.89
USB_ID  (via drill 0.3)
  Top 0.254: 17.91,27.43 18.41,27.94 26.16,27.94 26.42,28.19 v26.42,29.84
  Top 1.016: DEV_ID/HOST_ID.2 17.91,27.43
  Bottom 0.254: U1.38 27.03,29.23 v26.42,29.84
USB_SHIELD
  Top 1.016: 6.1,26.97 USB_DEV.SH4 1.7,26.97 0.99,26.27 USB_DEV.SH1 USB_DEV.SH2 0.99,20.09 1.31,19.77 USB_DEV.SH3 7.66,19.77 FB2.2
VCC  (via drill 0.3, 0.3 pad 0.25, 0.6, 0.6 pad 0.25)
  Top 0.254: U6.12 50.55,35.18
  Top 0.508: C8.1 R6.1 C13.1 19.68,18.03 19.43,18.03 | v29.72,8.51 C55.2 | v35.94,38.86 v38.86,38.86 41.27,38.86 42.29,39.88 | 43.56,40.01 43.56,40.26 42.67,40.26 42.29,39.88 | v36.83,18.03 v41.02,18.03 | 57.53,42.16 C5.1 | v49.91,35.18 50.55,35.18 C45.2 | RM2.2.1 v45.72,35.18 45.47,35.18 | 45.47,34.42 RM2.3.1 | v48.51,31.5 R32.2 | 45.47,28.7 45.21,28.96 v45.21,29.84 | 43.56,39.88 42.29,39.88 | v32.77,46.86 33.15,47.24 42.29,47.24 v43.56,45.97
  Top 0.762: v36.83,20.32 v32.13,20.32 v27.3,20.32 | RM3.4.2 v43.56,40.13 43.56,40.01 | 45.59,36.07 RM2.1.1 | RM2.4.1 45.72,33.53 45.47,33.78 45.47,34.42 45.47,35.18 45.47,36.07
  Top 1.016: L2.2 23.11,13.21 C14.1 v18.29,13.21 | v28.96,29.84 v28.96,27.05 26.92,25.02 v26.42,25.02 v21.08,25.02 | UEXT.1 16.51,40.01 v15.37,40.01 | 19.43,18.03 v18.29,18.03 v9.78,18.03 | 26.54,11.18 26.54,11.3 v29.72,11.3 v33.35,11.3 v35.45,11.3 v36.85,11.3 v54.74,11.3 | CD1.4 56.01,39.62 56.01,42.16 | 56.01,42.16 CD1.1 | v61.34,44.07 60.58,43.31 59.44,43.31 58.29,42.16 57.53,42.16 56.01,42.16 | v54.74,21.34 v54.74,23.11 | 45.59,36.07 45.47,36.07 44.2,36.07 43.56,36.7 43.56,39.88 43.56,40.01 | L6.2 C46.2 v54.74,27.43 v49.4,27.43 46.74,27.43 45.47,28.7
  Top 1.27: L2.2 23.88,12.9 L3.1 23.88,11.18 26.54,11.18 C54.2 26.54,8.38
  Bottom 0.254: v28.96,29.84 29.07,29.73 U1.39 | U1.34 29.14,27.23 v28.96,27.05 | U1.54 35.58,38.72 C40.1 | C38.1 36.7,21.21 36.08,21.83 U1.26 | 38.58,38.86 U1.60 | C37.1 44.45,29.84 43.56,30.73 U1.8
  Bottom 0.356: v33.35,11.3 LCD.6
  Bottom 0.406: v35.45,11.3 LCD.9 | v36.85,11.3 LCD.11 | R41.2 R42.2 R43.2
  Bottom 0.508: v28.96,29.84 C39.1 | C35.2 v28.96,27.05 28.96,26.16 29.21,25.91 C36.1 29.46,27.05 | 16.26,45.34 R48.2 | 16.26,43.81 R45.2 | 16.26,44.7 R47.2 | 9.02,16.51 R27.2 | 9.02,14.48 RM1.2.2 | 9.02,13.72 RM1.3.2 | 9.02,12.83 RM1.4.2 | R26.2 11.3,7.37 11.3,7.11 | R31.2 11.3,6.6 11.3,7.11 | 11.05,7.11 11.3,7.11 | R56.1 10.29,3.3 | 16.89,41.91 5V/3.3V.3 | 29.84,20.32 C82.1 | C38.1 v36.83,20.32 v36.83,18.03 | v29.72,11.3 v29.72,8.51 | v35.94,38.86 C40.1 | v38.86,38.86 38.58,38.86 C41.1 | v41.02,18.03 R41.2 | v45.72,35.18 v49.91,35.18 | v45.21,29.84 C37.1 | v48.51,31.5 49.4,30.61 v49.4,27.43 | 15.62,42.16 R46.2 15.24,41.02 15.37,40.89
  Bottom 0.762: 16.26,41.91 16.89,41.91 | 30.86,20.32 29.84,20.32 | 30.86,20.32 CD2.1 | 30.86,20.32 v32.13,20.32 33.4,20.32 CD2.4 | v27.3,20.32 27.3,23.5 26.42,24.38 v26.42,25.02
  Bottom 1.016: 16.26,42.8 16.26,41.91 16.26,41.78 15.37,40.89 v15.37,40.01 15.37,37.21 15.88,36.7 22.99,36.7 23.88,35.81 23.88,33.91 21.84,31.88 21.84,25.78 v21.08,25.02 18.29,22.23 v18.29,18.03 v18.29,13.21 | 16.26,42.8 16.26,43.81 16.26,44.7 16.26,45.34 | 9.02,11.05 L5.1 | 9.02,11.05 9.02,12.83 9.02,13.72 9.02,14.48 9.02,16.51 9.02,17.27 v9.78,18.03 | 9.02,7.11 9.02,11.05 | 9.02,7.11 11.05,7.11 | 9.02,7.11 9.02,5.71 10.29,4.45 10.29,3.3 | v43.56,40.13 v43.56,45.97 43.56,48.39 44.2,49.02 61.85,49.02 62.36,48.51 ICSP.2 62.36,45.09 | 62.36,45.09 v61.34,44.07 | 62.36,45.09 73.66,45.09 75.44,43.31 78.23,43.31 78.99,42.55 78.99,24.89 77.22,23.11 v54.74,23.11 v54.74,27.43 | v54.74,11.3 v54.74,21.34 | 16.26,42.8 15.62,42.16 | FB3.2 32,46.1 v32.77,46.86
VCOMH1  (via drill 0.3)
  Top 0.508: C57.2 v46.35,8.51
  Bottom 0.406: v46.35,8.51 47.5,8.51 48.05,9.07 LCD.27
VDD  (via drill 0.3, 0.3 pad 0.25, 0.6)
  Top 0.508: C16.1 22.1,8.76 C15.1 | v40.51,22.23 v43.69,22.23 50.29,22.23 52.96,19.56 v58.67,19.56 58.67,19.68 59.94,20.95 63.37,20.95 v64.01,20.32
  Top 0.762: v22.86,7.75 22.86,9.02 | v53.21,1.91 54.36,0.76 62.36,0.76 64.14,2.54 64.14,8 | v64.01,20.32 64.01,16.26 63.75,16 v63.75,11.68 63.75,11.43 64.14,11.05 64.14,8 | 64.14,8 68.96,8 v70.74,6.22
  Top 1.016: L3.2 22.86,9.02 C15.1
  Bottom 0.254: U1.19 39.58,22.52 C44.1
  Bottom 0.508: R55.1 44.2,19.3 43.69,19.81 v43.69,22.23 | v40.51,22.23 C44.1 | v64.01,20.32 R2.2 | v58.67,19.56 R1.2 | U3.7 63.5,14.22 62.87,13.59 C1.1 v63.75,11.68 | 67.44,5.84 U4.6 | 67.44,5.84 C23.1 | 67.44,5.84 68.96,5.84 C24.1
  Bottom 0.762: v22.86,7.75 23.62,6.99 23.62,2.67 24.51,1.78 53.09,1.78 v53.21,1.91 | v70.74,6.22 C24.1

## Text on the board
Top: 2Layers PCB | 467 total errors | 359 errors
Bottom: 279 errors
tNames: GND | CANL | CANH | PIC32-EMZ64 | Rev. C | + | - | <C> 2018 | https://www.olimex.com | 5VDC_Only!!! | Made in Bulgaria
bNames: GND | CANL | CANH | RESET | 3.3V | GND | PGD | PGC | NC | + | - | 5VDC_Only!!!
